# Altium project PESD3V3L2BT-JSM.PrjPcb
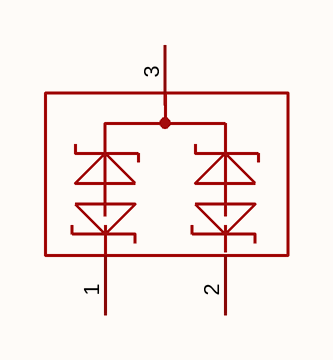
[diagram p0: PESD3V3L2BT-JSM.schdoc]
1 sheet, 1 parts. Net scope: global (net labels, ports and power ports of the same name join across sheets).

## Sheet PESD3V3L2BT-JSM.schdoc
size 127 x 101 mm

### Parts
D?  pesd3v3l2bt-jsm  [SOT-23-3_L2.9-W1.3-P1.90-LS2.4-BR]  (value not drawn)

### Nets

Not connected (* = marked no-connect by the designer): D? 1 2 3

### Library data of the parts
D? = pesd3v3l2bt-jsm: 极性:双向;反向截止电压(Vrwm):3.3V;钳位电压:7.5V;峰值脉冲电流(Ipp):-;峰值脉冲功率(Ppp):350W@8/20us;击穿电压(VBR):5.8V;; Manufacturer: JSMSEMI(杰盛微); AddInBom: yes; ModelId: c62791f0466c4ae2a892c056b845b0ca; ModelName: SOT-23-3P_L2.9-W1.3-H1.0-LS2.4-P0.95; ModelTransform: 98.425,114.173,0,180,0,0,0.0005,-0.0005,0; Polarity: 双向; Reverse Stand-Off Voltage (Vrwm): 3.3V; Clamping Voltage: 7.5V; Voltage - Breakdown: 5.8V; Reverse Leakage Current (Ir): 2uA; Number of Channels: 双路; level of protection: IEC 61000-4-4；IEC 61000-4-2; Type: ESD; Junction Capacitance: 120pF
